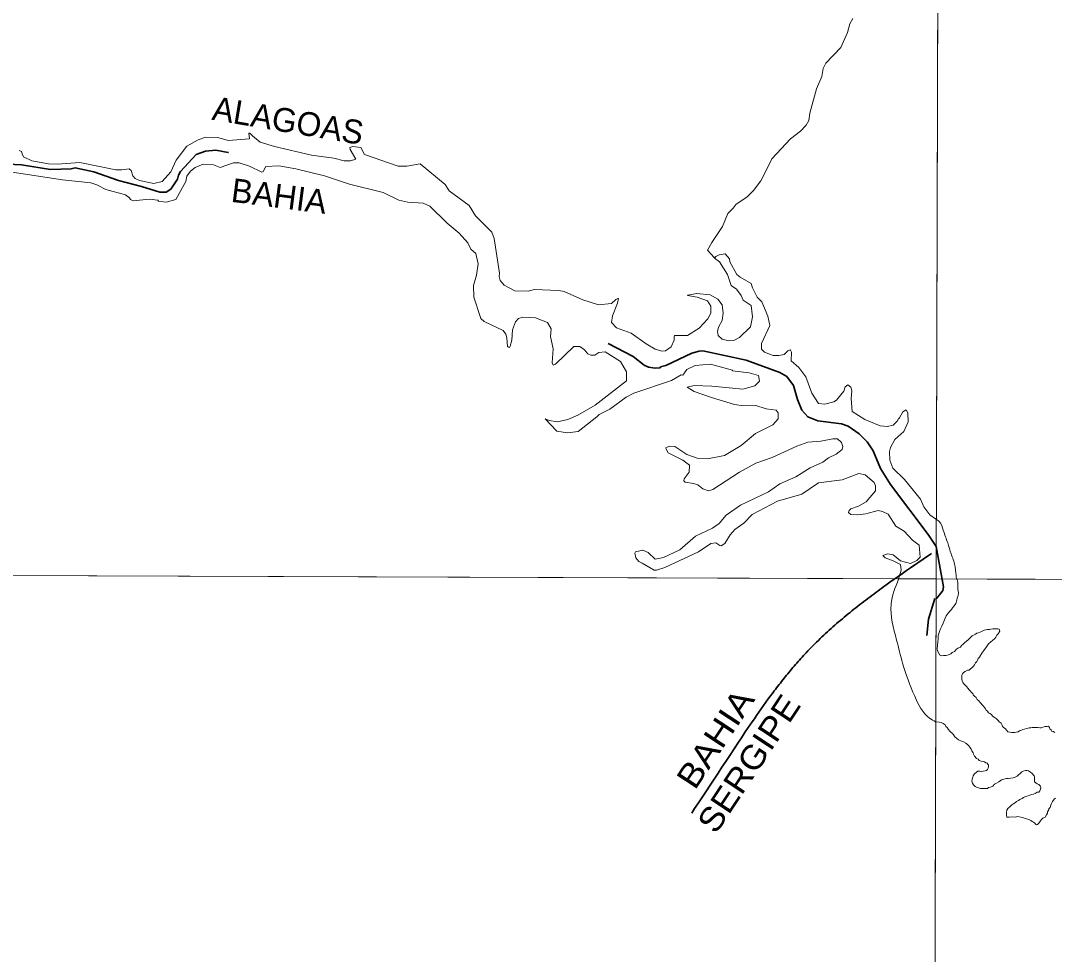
# Model space of a CAD drawing. Extents: x -1643653 to 4543381, y 1624270 to 13878484.
# Drawn here: x 582541 to 586012, y 8908709 to 8911844 of the extents above; entities that cross this region are included whole.
import ezdxf
from ezdxf.enums import TextEntityAlignment as Align

# ---------------------------------------------------------------- set-up
doc = ezdxf.new("R2010")
doc.units = 0
doc.header["$LTSCALE"] = 200
doc.linetypes.add('LONG_DASH_SHORT_DASH', pattern=[9.9, 6, -1.2, 1.5, -1.2])
doc.layers.add('6', color=7, linetype='Continuous', lineweight=13)
doc.layers.add('60', color=7, linetype='Continuous', lineweight=13)

msp = doc.modelspace()

# ---------------------------------------------------------------- linework, layer by layer
at = {"layer": '6'}
msp.add_line((574653.9, 8910009.3), (626625.7, 8909822.1), dxfattribs=at)
for points in [[(585656.3, 8924738.8), (585614.8, 8909969.8), (585573.6, 8896026.7)], [(585052, 8911356.7), (585064, 8911380), (585126, 8911447.6), (585159.2, 8911472.7), (585179.2, 8911493.5), (585188.1, 8911508.8), (585191, 8911533.8), (585213.2, 8911615.2), (585231.4, 8911656.6), (585235.7, 8911683), (585245, 8911701.2), (585295.1, 8911754.3), (585317.8, 8911804.3), (585325.3, 8911832.9), (585335.1, 8911850.8)], [(584641, 8910758.3), (584591.5, 8910794.6), (584542.4, 8910812.7), (584524.6, 8910830.5), (584528.2, 8910853.4), (584545.1, 8910894.9), (584548.4, 8910910.8), (584546.9, 8910911.2), (584539.2, 8910908.2), (584524.9, 8910894.4), (584481.6, 8910890), (584429.4, 8910906.1), (584366.4, 8910934.4), (584348.8, 8910937.6), (584265.8, 8910940.9), (584246.1, 8910935.6), (584201, 8910936.7), (584164.3, 8910955.8), (584151.3, 8910971.6), (584147.4, 8910984.7), (584148.7, 8910996.2), (584130.6, 8911112.6), (584123.4, 8911134.2), (584068.8, 8911188.8), (584046.7, 8911222.8), (583979.6, 8911272.1), (583966.5, 8911293.9), (583882.2, 8911363.2), (583838.3, 8911355.7), (583808.5, 8911355.2), (583696.2, 8911394.6), (583683, 8911417.9), (583657.1, 8911421.6), (583646.5, 8911418.1), (583648, 8911410.9), (583666.4, 8911379.1), (583648.5, 8911372.9), (583626.9, 8911373), (583592.4, 8911382), (583517.2, 8911392.7), (583393.6, 8911421.1), (583345.3, 8911435.9), (583319.1, 8911456.7), (583310.5, 8911466.5), (583307.1, 8911466.5), (583309.5, 8911446.9), (583237.7, 8911441.4), (583203.3, 8911451.7), (583163.4, 8911452.9), (583136.7, 8911443.9), (583099.1, 8911422.9), (583062.9, 8911375.8), (583045.7, 8911335.9), (583016.8, 8911303.6), (582988.5, 8911297.2), (582940.1, 8911306.8), (582925.6, 8911313.4), (582918.1, 8911322.8), (582911.8, 8911341.3), (582906, 8911346.2), (582880.8, 8911342.6), (582861.2, 8911343.5), (582740.1, 8911367.8), (582663.3, 8911361.8), (582634.4, 8911363.2)], [(582634.4, 8911363.2), (582579.1, 8911373.6), (582550.8, 8911386.8), (582545.9, 8911396.6), (582544.2, 8911404.8), (582536.6, 8911407.9)], [(583062.7, 8911243.2), (583095.4, 8911304), (583099.7, 8911321.3), (583111.2, 8911338.2), (583126.6, 8911350.5), (583153.6, 8911361.8), (583188.6, 8911359.7), (583211.3, 8911350.5), (583256.3, 8911366.4), (583274.7, 8911366.4), (583309.8, 8911355.4), (583350.5, 8911335.3), (583355.5, 8911337.7), (583364.5, 8911354.3), (583407.8, 8911356.6), (583465.7, 8911346.7), (583560.9, 8911323.1), (583645.6, 8911294.8), (583758.9, 8911266.5), (583811.2, 8911241.3), (583841, 8911234.7), (583892.8, 8911231.2), (583915.5, 8911221.6), (583973.2, 8911163.9), (584013.1, 8911130.1), (584043.2, 8911097.8), (584052.5, 8911077.1), (584070.1, 8911062), (584076.9, 8911026.9), (584071.6, 8910989.7), (584061.4, 8910954.7), (584062.8, 8910915.7), (584086.9, 8910843.7), (584097.7, 8910833.8), (584161, 8910803.5), (584170.1, 8910791), (584173.9, 8910778.7), (584176.1, 8910750.2), (584178.9, 8910747.1), (584182.3, 8910746.8), (584184.8, 8910750.9), (584190.7, 8910771), (584192.8, 8910806.3), (584203.3, 8910833), (584212.9, 8910843.5), (584227.1, 8910848.6), (584269.4, 8910846.1), (584310.4, 8910830.5), (584322.4, 8910808.9), (584320.2, 8910783.4), (584328.8, 8910742.2), (584326.1, 8910695.4), (584329.5, 8910687), (584337.2, 8910690.8), (584398.2, 8910749.5), (584418.5, 8910749.9), (584434, 8910739.1), (584445.3, 8910725.4), (584455.6, 8910720.9), (584468.6, 8910721), (584483.1, 8910729.5), (584503.5, 8910731.6), (584555.8, 8910699.3), (584575.1, 8910664.3), (584575, 8910635.1)], [(584869.8, 8911049.2), (584847.8, 8911073.4), (584861.8, 8911099.2), (584897.9, 8911152.3), (584915.7, 8911196.5), (584933.9, 8911213.8), (584944.2, 8911228.3), (584979.9, 8911250.9), (585001.8, 8911273.7), (585026.2, 8911306.6), (585052, 8911356.7)], [(582512.2, 8911335.3), (582681.7, 8911309.6), (582777, 8911299.2), (582796.6, 8911293), (582827.3, 8911276.8), (582893.4, 8911258.7), (582906.7, 8911249.2), (582909.6, 8911243.5), (582918.9, 8911239.1), (582972.2, 8911244.5), (583002.2, 8911240.8), (583003.6, 8911237.4), (583029.7, 8911234.8), (583062.7, 8911243.2)], [(585613, 8910170.9), (585594.1, 8910185.2), (585574.1, 8910212), (585562.3, 8910236.9), (585508.4, 8910303.8), (585469.5, 8910341.1), (585459.3, 8910368.4), (585458.6, 8910397.8), (585461.4, 8910410.8), (585476.2, 8910437.1), (585506.5, 8910464.7), (585521.5, 8910496.5), (585520.3, 8910527.4), (585514.3, 8910537.5), (585503.6, 8910530.2), (585491.9, 8910510), (585489.3, 8910507.2), (585484.3, 8910499.4), (585470.6, 8910485.7), (585452.1, 8910481.5), (585427.8, 8910483.5), (585376, 8910505.3), (585332.8, 8910531.9), (585330.2, 8910575.4), (585332.3, 8910601), (585328.2, 8910613.7), (585318.2, 8910620.8), (585310.2, 8910614), (585304.7, 8910600.1), (585280.3, 8910570.1), (585271.3, 8910563.7), (585242, 8910556.1), (585220.2, 8910558.3), (585197.6, 8910593.2), (585177.1, 8910647.8), (585154, 8910678.9), (585128, 8910701.8), (585129, 8910730.6), (585125.8, 8910737.8), (585125, 8910738.2), (585117.6, 8910735.4), (585105.2, 8910723.1), (585087.3, 8910719.3), (585068, 8910719.9), (585038.3, 8910731.3), (585028.3, 8910741.3), (585028.9, 8910759.6), (585057.1, 8910820), (585049.8, 8910852.2), (585029.9, 8910899.7), (585014.7, 8910915.8), (584998.2, 8910946.8), (584994.6, 8910961.8), (584956.8, 8910982.3), (584945.7, 8910992), (584922.3, 8911033.6), (584921.4, 8911043.8), (584906.8, 8911060.5), (584886.1, 8911057.1), (584874.9, 8911052.5), (584870.9, 8911046.7), (584887.2, 8911034), (584914.8, 8910992.1), (584927.4, 8910954.3), (584944.4, 8910942.7)], [(584944.4, 8910942.7), (584960.4, 8910920.9), (584967.4, 8910905.9), (584993.8, 8910887.8), (584999.1, 8910849), (584992.2, 8910815.8), (584954.7, 8910780.4), (584936, 8910769.9), (584918.9, 8910768.5), (584896.4, 8910774.5), (584883, 8910786.4), (584881.5, 8910800.6), (584884.8, 8910814.9), (584897.1, 8910837.6), (584900.6, 8910861.3), (584897, 8910889.5), (584881.7, 8910909.3), (584856.5, 8910923.9), (584810.8, 8910927.6), (584781.5, 8910922.4), (584780, 8910920.9), (584812.5, 8910915), (584847.9, 8910902.9), (584859.2, 8910885.3), (584858.6, 8910861.6), (584848.5, 8910843.3), (584819.4, 8910811.9), (584780.6, 8910786.7), (584737.2, 8910786.5), (584735.1, 8910781.6), (584735.5, 8910771.3), (584725.7, 8910749.3), (584706.1, 8910735.8), (584694.1, 8910733.8), (584672.2, 8910740.6), (584641, 8910758.3)], [(584575, 8910635.1), (584469.8, 8910553.2), (584412.1, 8910519.2), (584378.1, 8910504.3), (584343.7, 8910496.8), (584315.6, 8910501), (584302.5, 8910506.7), (584341.7, 8910466.1), (584377, 8910460), (584413.4, 8910464.9), (584476.2, 8910513.3), (584483.2, 8910521.7), (584519.5, 8910539.6), (584574.1, 8910579.6), (584600.3, 8910593.5), (584727.1, 8910635.6), (584758.7, 8910654.2), (584764.1, 8910654.1), (584777.8, 8910672.8), (584805.8, 8910686.5), (584857.1, 8910690.5), (584931.6, 8910670.4), (584931.7, 8910668.3), (584987.4, 8910661.7), (585018.3, 8910652.2), (585022.5, 8910633.9), (585006, 8910617.9), (584965.8, 8910606.8), (584862.5, 8910616.7)], [(584862.5, 8910616.7), (584802.7, 8910619.4), (584779.5, 8910612.9), (584802.7, 8910598.3), (584861, 8910578.3), (584938.2, 8910555.3), (584968.8, 8910550.7), (585009.7, 8910552), (585044.2, 8910540.8), (585078.1, 8910536.3), (585084.6, 8910527), (585084.6, 8910506.7), (585066.6, 8910486.9), (585008.8, 8910457.8), (584961, 8910417.7), (584904.5, 8910384.2), (584847.7, 8910372.4), (584813.3, 8910375.5), (584777.6, 8910387.8), (584738.3, 8910414.6), (584719.6, 8910415), (584707.3, 8910410.1), (584708.3, 8910404.7), (584715.3, 8910392.9), (584764.8, 8910368.3), (584787.4, 8910351.4), (584785.9, 8910327.6), (584769.2, 8910305.8), (584767.6, 8910298.8), (584772.9, 8910294.4), (584800, 8910289.5), (584814.7, 8910285.1), (584831.6, 8910271.7), (584850.3, 8910265.6), (584865.5, 8910269.3), (584954.5, 8910328.5), (585009.6, 8910357.9), (585064.1, 8910377.6), (585147.9, 8910415.2), (585184.6, 8910428.3), (585228.5, 8910431.7), (585267.9, 8910439.7), (585283.9, 8910439.8), (585297.3, 8910428.1), (585301.8, 8910413.6), (585299.8, 8910404), (585279.9, 8910388.4), (585254.1, 8910375.6), (585234.4, 8910361.7), (585192.5, 8910342.6), (585144.1, 8910312.1), (585090.8, 8910289), (585052.1, 8910261.8), (584958.3, 8910216.9), (584910.5, 8910183.5), (584886.5, 8910155.6), (584864.3, 8910139.8), (584806.9, 8910113.4), (584754.7, 8910067.2), (584700, 8910041.6), (584672.2, 8910035.9), (584648.3, 8910057.9), (584630.4, 8910065.7), (584605.9, 8910061), (584603.9, 8910056.1)], [(584603.9, 8910056.1), (584607.2, 8910039.8), (584616.9, 8910028.5), (584628.5, 8910021.9), (584668.8, 8909998.9), (584676.7, 8909998.9), (584704, 8910007.6), (584817.2, 8910060.3), (584858.8, 8910088.5), (584875.1, 8910090.6), (584888.6, 8910081.7), (584893.5, 8910080.6), (584905.8, 8910088), (584923.7, 8910117.4), (584939.2, 8910135.5), (584969.7, 8910156.6), (584997.7, 8910186.3), (585082.5, 8910230.4), (585164.2, 8910254), (585220.6, 8910292.1), (585299.9, 8910302.5), (585355.9, 8910323.7), (585377.1, 8910318.9), (585407.1, 8910293.7), (585411.8, 8910281.8), (585411.3, 8910265.8), (585380.1, 8910228.3), (585354.8, 8910214.1), (585328.7, 8910204.3), (585323, 8910199), (585320.6, 8910192.2), (585329.2, 8910186.2), (585351.9, 8910184.5), (585378.8, 8910187.8), (585420.4, 8910199.1), (585435, 8910196.4)], [(585435, 8910196.4), (585454.1, 8910186.9), (585480.4, 8910146.2), (585507.6, 8910130.2), (585536, 8910099.4), (585557.7, 8910083.3), (585561.6, 8910042.2), (585550.1, 8910031.9), (585529.2, 8910021.5), (585495.8, 8910030.1), (585470.4, 8910050.8), (585453.4, 8910054.2), (585436.7, 8910048.7), (585443.6, 8910040.4), (585470.9, 8910030.2), (585495.8, 8910018), (585497.8, 8909999), (585489.3, 8909969)], [(585620.4, 8909758.5), (585621.7, 8909767), (585622.4, 8909778.7), (585626.9, 8909793), (585629.5, 8909802.2), (585634.1, 8909811.3), (585639.3, 8909821), (585640.6, 8909826.9), (585645.2, 8909837.3), (585649.1, 8909845.1), (585655.6, 8909854.9), (585662.1, 8909862.1), (585666.7, 8909866.6), (585669.9, 8909872.5), (585675.8, 8909879), (585681, 8909887.4), (585684.9, 8909897.8), (585686.2, 8909905), (585688.8, 8909914.1), (585690.1, 8909923.2), (585688, 8909935.1), (585688.1, 8909940.1), (585688.1, 8909944.1), (585688.2, 8909950.1), (585687.7, 8909956.1), (585686.8, 8909963.1), (585685.3, 8909967.1), (585683.7, 8909969.3)], [(585819.6, 8909497.1), (585816.6, 8909501.1), (585810.2, 8909505.2), (585804.7, 8909508.7), (585801.2, 8909514.7), (585795.8, 8909517.3), (585791.3, 8909520.3), (585787.8, 8909525.8), (585783.3, 8909529.4), (585780.4, 8909533.9), (585777.4, 8909537.9), (585773.9, 8909542.5), (585769.5, 8909546.5), (585765, 8909552), (585761.5, 8909556.1), (585758.1, 8909560.1), (585753.1, 8909565.1), (585749.6, 8909571.7), (585743.7, 8909575.7), (585739.7, 8909580.2), (585738.2, 8909584.3), (585734.3, 8909588.3), (585730.3, 8909592.8), (585725.8, 8909596.9), (585721.9, 8909602.9), (585718.4, 8909606.9), (585714.9, 8909610.9), (585708.5, 8909617.5), (585704.5, 8909621.5), (585703, 8909626.6), (585701.6, 8909634.6), (585701.2, 8909642.1), (585701.2, 8909646.6), (585703.2, 8909651.1), (585706.8, 8909655.6), (585712.8, 8909659), (585720.3, 8909663.5), (585725.8, 8909663.4), (585730.4, 8909667.4), (585735.4, 8909671.4), (585740.9, 8909676.4), (585743.5, 8909681.4), (585747, 8909688.3), (585752.1, 8909692.8), (585753.6, 8909697.3), (585756.1, 8909701.8), (585760.7, 8909706.3), (585768.6, 8909719.7), (585774.8, 8909729.4), (585784.1, 8909741.8), (585791.2, 8909751.1), (585799.2, 8909758.6), (585804.3, 8909762.5), (585811.8, 8909769.5), (585815.4, 8909774), (585819.4, 8909780.5), (585823.5, 8909784.9), (585829.5, 8909793.9), (585827.1, 8909800.4), (585822.6, 8909802.5), (585816.1, 8909802.5), (585810.1, 8909802.1), (585806.1, 8909801.6), (585798.6, 8909801.1), (585794.6, 8909800.2), (585788.1, 8909799.2), (585782, 8909798.2), (585776.5, 8909797.8), (585770, 8909793.8), (585763, 8909791.3), (585757, 8909788.9), (585751.4, 8909787.4), (585747.4, 8909784.4), (585740.4, 8909781), (585736.4, 8909778), (585727.9, 8909770.9), (585727.9, 8909770.9), (585721.4, 8909763.7), (585721.4, 8909763.7), (585711.6, 8909755.9), (585705.8, 8909750.7), (585705.8, 8909750.7), (585700.5, 8909745.5), (585696.6, 8909740.9), (585687.5, 8909737), (585682.3, 8909732.5), (585677.1, 8909725.3), (585668.6, 8909722.7), (585664.1, 8909718.2), (585656.9, 8909714.2), (585648.4, 8909712.9), (585640.3, 8909712.6), (585632.8, 8909711.7), (585632.8, 8909711.7), (585626.9, 8909714.9), (585623.7, 8909720.1), (585623.7, 8909720.1), (585619.8, 8909728.6), (585618.5, 8909735.1), (585619.8, 8909746.2), (585620.4, 8909758.5)], [(585613.4, 8909490.1), (585625.1, 8909488.8), (585632, 8909487.3), (585638.9, 8909484.6), (585645, 8909479.2), (585648.1, 8909474.3), (585652.7, 8909470.4), (585655.8, 8909465.1), (585655.8, 8909465.1), (585661.5, 8909458.2), (585661.5, 8909458.2), (585665.7, 8909454.3), (585670.5, 8909450.3), (585674, 8909446.2), (585678.4, 8909439.2), (585683.4, 8909434.7), (585690.2, 8909429.4), (585690.2, 8909429.4), (585700.8, 8909424.5), (585707.3, 8909422), (585715.3, 8909418.4), (585721.7, 8909412.9), (585724.7, 8909408.8), (585728.2, 8909404.8), (585733.1, 8909397.8), (585735.6, 8909391.8), (585739.5, 8909385.2), (585741, 8909381.2), (585744.5, 8909374.2), (585750.9, 8909366.6), (585755.9, 8909364.6), (585759.3, 8909359.6), (585766.3, 8909358), (585772.8, 8909356), (585777.3, 8909354.9), (585781.8, 8909351.9), (585786.3, 8909350.9), (585790.8, 8909344.3), (585790.7, 8909339.8), (585789.7, 8909334.3), (585788.1, 8909329.3), (585784.7, 8909326.6), (585780, 8909325.2), (585773.2, 8909324.6), (585768.1, 8909323.4), (585762.1, 8909323.5), (585755.1, 8909323.5), (585750.6, 8909320.6), (585744, 8909315.1), (585740, 8909308.1), (585738.2, 8909303.8), (585735.8, 8909297.5), (585735.1, 8909290.1), (585736.9, 8909283.3), (585740.3, 8909278.6), (585745.7, 8909272.5), (585752.7, 8909269.5), (585757.2, 8909267.9), (585764.6, 8909266.4), (585770.6, 8909265.8), (585779.7, 8909265.8), (585787.2, 8909266.2), (585791.2, 8909268.7), (585797.7, 8909270.2), (585805.2, 8909274.1), (585810.8, 8909280.6), (585818.3, 8909284.1), (585825.8, 8909288), (585830.4, 8909291.5), (585834.4, 8909295), (585838.4, 8909295.9), (585842.4, 8909296.9), (585846.9, 8909297.9), (585850.9, 8909299.4), (585858.4, 8909299.8), (585866, 8909300.8), (585873.5, 8909302.2), (585881, 8909304.2), (585887.5, 8909307.6), (585892.1, 8909312.1), (585896.1, 8909315.6), (585903.1, 8909321.6), (585907.2, 8909324.5), (585914.7, 8909326), (585919.7, 8909325.9), (585925.2, 8909324.9), (585931.9, 8909320.9), (585938.1, 8909316.6), (585944.2, 8909308.9), (585944.2, 8909308.9), (585945.5, 8909304.8), (585945.5, 8909297.7), (585945.4, 8909293.7), (585945.9, 8909288.7), (585949.9, 8909284.7), (585954.3, 8909281.2), (585960.3, 8909279.1), (585964.5, 8909274.8), (585966.8, 8909269.6), (585965.2, 8909264.1), (585963.7, 8909258.1)], [(586013.9, 8909454.2), (586008.4, 8909456.8), (586002.9, 8909458.3), (586000.9, 8909462.3), (585997, 8909466.4), (585996, 8909470.4), (585992, 8909474.9), (585988, 8909474.4), (585981.5, 8909474), (585977.5, 8909473), (585973.5, 8909472.1), (585967.5, 8909470.1), (585963.5, 8909470.1), (585957, 8909470.2), (585951, 8909470.2), (585946.5, 8909470.2), (585942, 8909470.2), (585938, 8909470.3), (585933.5, 8909469.8), (585927.9, 8909469.3), (585923.9, 8909468.4), (585917.9, 8909466.9), (585912.4, 8909464.9), (585906.4, 8909463.5), (585901.9, 8909462), (585895.3, 8909459), (585890.8, 8909456.1), (585883.8, 8909454.6), (585879.8, 8909454.1), (585873.3, 8909454.2), (585869.3, 8909454.2), (585862.3, 8909455.3), (585856.3, 8909455.8), (585852.8, 8909460.3), (585846.9, 8909466.9), (585841.9, 8909470.9), (585838.5, 8909474.9), (585836, 8909481), (585833, 8909485.5), (585827.1, 8909489.5), (585824.6, 8909493.6), (585819.6, 8909497.1)], [(585963.7, 8909258.1), (585959.6, 8909253.6), (585954.1, 8909253.1), (585948.1, 8909249.2), (585941.6, 8909247.2), (585936.1, 8909245.2), (585930, 8909243.3), (585924, 8909240.8), (585915, 8909238.9), (585908.5, 8909235.9), (585903.9, 8909231.9), (585895.9, 8909228.5), (585891.9, 8909225.5), (585885.4, 8909222), (585881.3, 8909219.1), (585875.8, 8909215.6), (585869.8, 8909210.6), (585864.2, 8909205.6), (585856.4, 8909198.5), (585853, 8909192.6), (585851.5, 8909186.3), (585851.5, 8909186.3), (585851.5, 8909176.6), (585852.6, 8909169.2)], [(585852.6, 8909169.2), (585860.8, 8909169.9), (585871.2, 8909170.3), (585880.2, 8909169.9), (585889.8, 8909171.4), (585899.2, 8909169.9), (585908.1, 8909167.3), (585914.4, 8909165.4), (585918.9, 8909164.3), (585926.3, 8909162.1), (585926.3, 8909162.1), (585932.7, 8909158.8), (585937.5, 8909155.4), (585941.6, 8909152.4), (585946.4, 8909149.8), (585948.7, 8909145.7), (585952.4, 8909144.2), (585956.1, 8909145.3), (585960.1, 8909149.8), (585965.2, 8909157.7), (585969.2, 8909162.2), (585973.3, 8909165.7), (585980.8, 8909169.6), (585985.3, 8909177.1), (585988.9, 8909183.6), (585989.4, 8909187.6), (585993.5, 8909194.1), (585994, 8909198.1), (585997.6, 8909202.6), (586000.1, 8909209.6), (586002.2, 8909215.6), (586005.7, 8909222.1), (586011.8, 8909229.5), (586015.8, 8909233.5)]]:
    msp.add_lwpolyline(points, dxfattribs=at)
for points in [[(585645.8, 8921027.3), (574684.9, 8921064.7), (574653.9, 8910009.3), (585614.8, 8909969.8)], [(596575.8, 8909932.4), (585614.8, 8909969.8), (585583.8, 8898914.4), (596544.8, 8898874.9)]]:
    msp.add_lwpolyline(points, close=True, dxfattribs=at)
at = {"layer": '6', "linetype": 'LONG_DASH_SHORT_DASH', "lineweight": 35}
for points in [[(582496.6, 8911362.4), (582544.5, 8911359.4), (582641.4, 8911343.8), (582710.6, 8911346), (582724.4, 8911349.4), (582786.7, 8911336.4), (582869.7, 8911307.5), (582946.6, 8911287.2), (583008.9, 8911268.1), (583029.6, 8911268.6), (583045.2, 8911277.6), (583067.7, 8911311.3), (583070.7, 8911325.2), (583077.6, 8911337.3), (583130.3, 8911394.8), (583161.9, 8911405.6), (583196.6, 8911409.1), (583238, 8911401.7), (583238.9, 8911401.7)], [(584514, 8910760.2), (584597.3, 8910716), (584635, 8910687.1), (584649.2, 8910681), (584671.7, 8910677.1), (584688.5, 8910678.4), (584689.9, 8910681.4), (584707.2, 8910685.8), (584795.4, 8910727.2), (584819.5, 8910734.6), (584831.7, 8910735), (584977.8, 8910704.3), (585090.2, 8910662.8), (585114.4, 8910648.6), (585135.7, 8910619.1), (585149.9, 8910572.1), (585164.6, 8910536.6), (585184.9, 8910513.7), (585218.4, 8910500.7), (585296.9, 8910489.9), (585319.4, 8910482.1), (585356.6, 8910456.1), (585383.4, 8910429.4), (585403.7, 8910399.5), (585428.8, 8910340.2), (585462.1, 8910286.2), (585588.3, 8910118.5), (585615.1, 8910078.7)], [(585615.1, 8910078.7), (585640.3, 8909942.8), (585637.2, 8909930.8), (585631.7, 8909922.3), (585625.6, 8909914.8), (585619, 8909906.4), (585614.6, 8909902.8)], [(585583.7, 8909780.1), (585589.5, 8909834.4), (585611.1, 8909903.9)]]:
    msp.add_lwpolyline(points, dxfattribs=at)
at = {"layer": '6'}
for points in [[(585683.7, 8909969.3), (585680.5, 8909997.4), (585678.2, 8910014.6), (585665.5, 8910053.6), (585654.1, 8910090.4), (585639.2, 8910132.8), (585625.4, 8910162.7), (585613, 8910170.9)], [(585489.3, 8909969), (585463.9, 8909884.3), (585482.4, 8909764.2), (585502.7, 8909686.5), (585543.4, 8909575.6), (585593.3, 8909501.7), (585613.4, 8909490.1)]]:
    msp.add_spline(points, degree=3, dxfattribs=at)
at = {"layer": '6', "linetype": 'LONG_DASH_SHORT_DASH', "lineweight": 35}
msp.add_spline([(585599.5, 8910054.8), (585178.8, 8909721.7), (584922.2, 8909376.8), (584712.9, 8909059.8)], degree=3, dxfattribs=at)
at = {"layer": '60', "lineweight": 25}
msp.add_spline([(814781, 9009175.5), (814787.2, 9009173.4), (814796.9, 9009173.4), (814799.4, 9009172.4), (814805.1, 9009174.5), (814805.6, 9009176.5), (814811.7, 9009179.5), (814811.7, 9009179.5), (814801.5, 9009181), (814790.7, 9009181.5), (814784.1, 9009183.1), (814777.4, 9009185.1), (814778.4, 9009175.5)], degree=3, dxfattribs=at)

# ---------------------------------------------------------------- texts
at = {"layer": '6'}
for s, rotation, p in [('ALAGOAS', 350.452, (583432.5, 8911469.1)), ('BAHIA', 352.646, (583404, 8911215.6))]:
    msp.add_text(s, height=80, rotation=rotation, dxfattribs=at).set_placement(p, align=Align.CENTER)
for s, width, p in [('BAHIA', 1.15, (584907.2, 8909411.3)), ('SERGIPE', 1.1, (585019.6, 8909327.4))]:
    msp.add_text(s, height=80, rotation=56.48, dxfattribs=dict(at, width=width)).set_placement(p, align=Align.CENTER)

doc.saveas('drawing.dxf')
